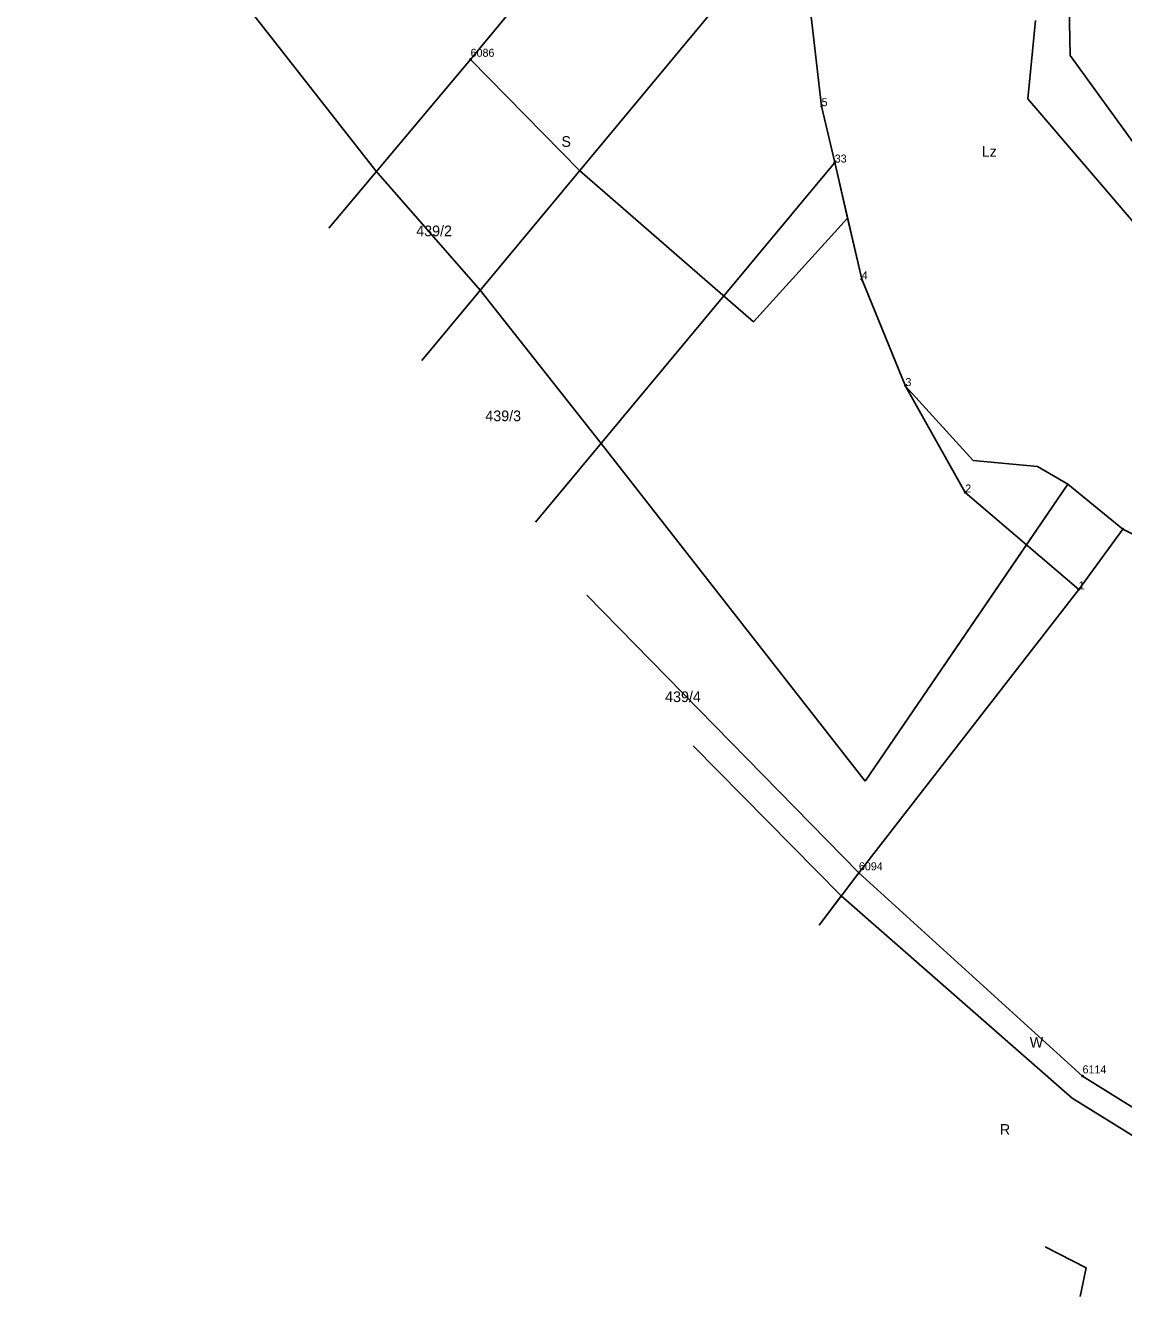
# Model space of a CAD drawing. Extents: x 7465393 to 7466459, y 5491258 to 5492404.
# Drawn here: x 7465576.1 to 7465730.4, y 5491691.2 to 5491869.8 of the extents above; entities that cross this region are included whole.
import ezdxf

# ---------------------------------------------------------------- set-up
doc = ezdxf.new("R2010")
doc.units = 0
for name, color, linetype in [('203-punkt graniczny', 7, 'Continuous'), ('203-punkt graniczny-Atr103', 7, 'Continuous'), ('210-oznaczenie konturu użytku gruntowego', 7, 'Continuous'), ('211-numer działki ewidencyjnej', 7, 'Continuous'), ('217-kontur klasyfikacyjny', 7, 'Continuous'), ('218-kontur użytku gruntowego', 7, 'Continuous'), ('219-działka ewidencyjna', 7, 'Continuous')]:
    doc.layers.add(name, color=color, linetype=linetype)

# ---------------------------------------------------------------- blocks, each defined once
blk = doc.blocks.new('203')
blk.add_circle((0, 0), 0.09)

msp = doc.modelspace()

# ---------------------------------------------------------------- linework, layer by layer
at = {"layer": '217-kontur klasyfikacyjny'}
for points in [[(7465625.3, 5491849.4), (7465576.07, 5491912.24)], [(7465687.94, 5491858.48), (7465685.19, 5491882.04)], [(7465689.78, 5491850.55), (7465687.94, 5491858.48)], [(7465691.59, 5491842.73), (7465689.78, 5491850.55)], [(7465639.95, 5491832.62), (7465625.3, 5491849.4)], [(7465693.58, 5491834.16), (7465691.59, 5491842.73)], [(7465656.98, 5491811.09), (7465639.95, 5491832.62)], [(7465699.72, 5491819.15), (7465693.58, 5491834.16)], [(7465709.23, 5491808.69), (7465699.72, 5491819.15)], [(7465694.07, 5491763.64), (7465656.98, 5491811.09)], [(7465718.27, 5491807.82), (7465709.23, 5491808.69)], [(7465722.54, 5491805.34), (7465718.27, 5491807.82)], [(7465722.54, 5491805.34), (7465716.74, 5491796.83)], [(7465730.26, 5491799.05), (7465722.54, 5491805.34)], [(7465738.53, 5491794.95), (7465730.26, 5491799.05)], [(7465716.74, 5491796.83), (7465694.07, 5491763.64)], [(7465654.96, 5491789.76), (7465693.18, 5491750.72)], [(7465690.71, 5491747.49), (7465669.87, 5491768.57)], [(7465693.18, 5491750.72), (7465724.6, 5491722.18)], [(7465723.13, 5491719.07), (7465690.71, 5491747.49)], [(7465724.6, 5491722.18), (7465735.87, 5491715.12)], [(7465735.31, 5491711.53), (7465723.13, 5491719.07)], [(7465719.36, 5491698.2), (7465725.13, 5491695.24)], [(7465725.13, 5491695.24), (7465724.29, 5491691.2)]]:
    msp.add_lwpolyline(points, dxfattribs=at)
at = {"layer": '218-kontur użytku gruntowego'}
for points in [[(7465625.3, 5491849.4), (7465576.07, 5491912.24)], [(7465669.25, 5491902.01), (7465638.62, 5491865.05)], [(7465687.94, 5491858.48), (7465685.19, 5491882.04)], [(7465722.63, 5491877.26), (7465722.85, 5491865.62)], [(7465717.99, 5491870.52), (7465716.91, 5491859.52)], [(7465638.62, 5491865.05), (7465653.93, 5491849.45)], [(7465722.85, 5491865.62), (7465737.59, 5491845.31)], [(7465716.91, 5491859.52), (7465733.41, 5491840.24)], [(7465689.78, 5491850.55), (7465687.94, 5491858.48)], [(7465691.59, 5491842.73), (7465689.78, 5491850.55)], [(7465639.95, 5491832.62), (7465625.3, 5491849.4)], [(7465653.93, 5491849.45), (7465678.39, 5491828.19)], [(7465678.39, 5491828.19), (7465691.59, 5491842.73)], [(7465693.58, 5491834.16), (7465691.59, 5491842.73)], [(7465656.98, 5491811.09), (7465639.95, 5491832.62)], [(7465699.72, 5491819.15), (7465693.58, 5491834.16)], [(7465709.23, 5491808.69), (7465699.72, 5491819.15)], [(7465694.07, 5491763.64), (7465656.98, 5491811.09)], [(7465718.27, 5491807.82), (7465709.23, 5491808.69)], [(7465722.54, 5491805.34), (7465718.27, 5491807.82)], [(7465722.54, 5491805.34), (7465694.07, 5491763.64)], [(7465730.26, 5491799.05), (7465722.54, 5491805.34)], [(7465738.53, 5491794.95), (7465730.26, 5491799.05)], [(7465654.96, 5491789.76), (7465693.18, 5491750.72)], [(7465669.87, 5491768.57), (7465690.71, 5491747.49)], [(7465693.18, 5491750.72), (7465724.6, 5491722.18)], [(7465687.58, 5491743.39), (7465690.71, 5491747.49)], [(7465690.71, 5491747.49), (7465723.13, 5491719.07)], [(7465724.6, 5491722.18), (7465735.87, 5491715.12)], [(7465723.13, 5491719.07), (7465735.31, 5491711.53)], [(7465719.36, 5491698.2), (7465725.13, 5491695.24)], [(7465725.13, 5491695.24), (7465724.29, 5491691.2)]]:
    msp.add_lwpolyline(points, dxfattribs=at)
at = {"layer": '219-działka ewidencyjna'}
for points in [[(7465638.62, 5491865.05), (7465669.25, 5491902.01)], [(7465631.75, 5491822.76), (7465687.06, 5491889.31)], [(7465685.19, 5491882.04), (7465687.94, 5491858.48)], [(7465618.7, 5491841.33), (7465638.62, 5491865.05)], [(7465687.94, 5491858.48), (7465689.78, 5491850.55)], [(7465647.76, 5491800), (7465689.78, 5491850.55)], [(7465689.78, 5491850.55), (7465693.58, 5491834.16)], [(7465693.58, 5491834.16), (7465699.72, 5491819.15)], [(7465699.72, 5491819.15), (7465708.12, 5491804.2)], [(7465708.12, 5491804.2), (7465724.07, 5491790.57)], [(7465724.07, 5491790.57), (7465730.26, 5491799.05)], [(7465730.26, 5491799.05), (7465751.15, 5491788.7)], [(7465724.07, 5491790.57), (7465693.18, 5491750.72)], [(7465687.58, 5491743.39), (7465693.18, 5491750.72)], [(7465693.18, 5491750.72), (7465724.6, 5491722.18)], [(7465724.6, 5491722.18), (7465735.87, 5491715.12)]]:
    msp.add_lwpolyline(points, dxfattribs=at)

# ---------------------------------------------------------------- block references
at = {"layer": '203-punkt graniczny'}
for p in [(7465638.62, 5491865.05), (7465687.94, 5491858.48), (7465689.78, 5491850.55), (7465693.58, 5491834.16), (7465699.72, 5491819.15), (7465708.12, 5491804.2), (7465730.26, 5491799.05), (7465724.07, 5491790.57), (7465693.18, 5491750.72), (7465724.6, 5491722.18)]:
    msp.add_blockref('203', p, dxfattribs=at)

# ---------------------------------------------------------------- texts
at = {"layer": '203-punkt graniczny-Atr103'}
for s, height, p in [('6086', 1.125, (7465638.62, 5491865.42)), ('5', 1.12, (7465687.94, 5491858.48)), ('33', 1.125, (7465689.78, 5491850.55)), ('4', 1.12, (7465693.58, 5491834.16)), ('3', 1.12, (7465699.72, 5491819.15)), ('2', 1.12, (7465708.12, 5491804.2)), ('1', 1.12, (7465724.07, 5491790.57)), ('6094', 1.125, (7465693.18, 5491751.1)), ('6114', 1.125, (7465724.6, 5491722.56))]:
    msp.add_text(s, height=height, dxfattribs=at).set_placement(p)
at = {"layer": '210-oznaczenie konturu użytku gruntowego'}
for s, p in [('S', (7465651.38, 5491852.76)), ('Lz', (7465710.43, 5491851.36)), ('W', (7465717.18, 5491726.18)), ('R', (7465712.99, 5491713.93))]:
    msp.add_text(s, height=1.5, dxfattribs=at).set_placement(p)
at = {"layer": '211-numer działki ewidencyjnej'}
for s, p in [('439/2', (7465630.98, 5491840.2)), ('439/3', (7465640.69, 5491814.21)), ('439/4', (7465665.95, 5491774.74))]:
    msp.add_text(s, height=1.5, dxfattribs=at).set_placement(p)

doc.saveas('drawing.dxf')
